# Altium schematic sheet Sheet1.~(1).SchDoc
size 431 x 279 mm; Date: Not shown in title block; ApprovedBy: Not shown in title block; CheckedBy: Not shown in title block; Author: Not shown in title block; CompanyName: Not shown in title block; Engineer: Not shown in title block; Organization: Not shown in title block; Address1: Not shown in title block; Address2: Not shown in title block; Address3: Not shown in title block; Address4: Not shown in title block; DocumentNumber: 1; Revision: Use project parameter SCH_Rev; SheetNumber: 2; SheetTotal: 3; PageSetup: Record=PageOptions¦CenterHorizontal=True¦CenterVertical=True¦PrintScale=1.00¦XCorrection=1.00¦YCorrection=1.00¦PrintKind=0¦BorderSize=5000000¦LeftOffset=0¦BottomOffset=0¦Orientation=2¦PaperLength=1000¦PaperWidth=1000¦Scale=100¦PaperSource=15¦PrintQuality=600¦MediaType=1¦DitherType=10¦PaperKind=Letter¦PrintScaleMode=1
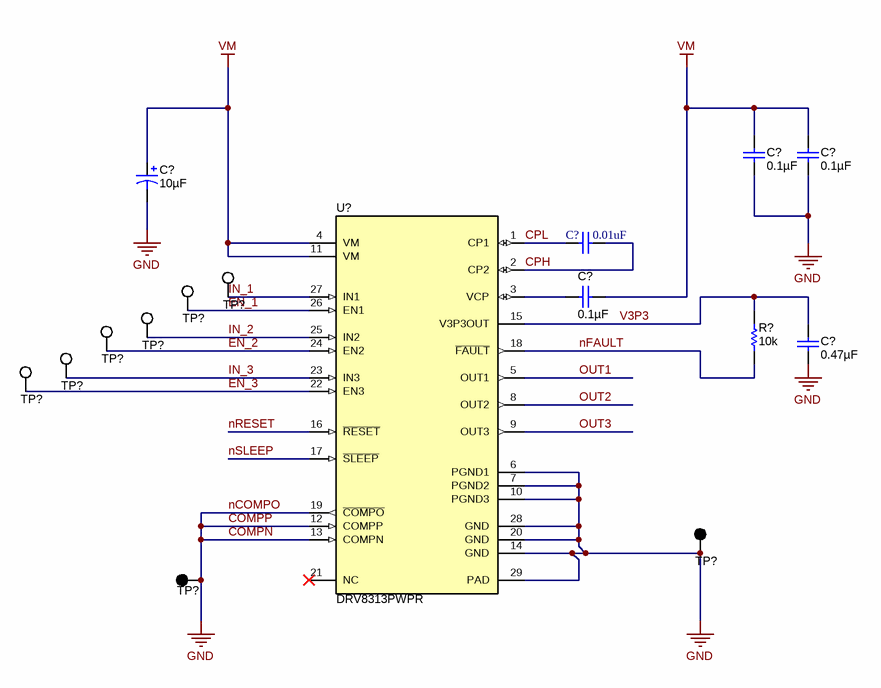
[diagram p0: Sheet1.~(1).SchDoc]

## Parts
(Parts that share a designator on the sheet are numbered #1, #2 ... from top to bottom, then left to right.)
C?#1  ValueDisplayed: 0.1µF  [0805_HV]  (hidden comment: C2012X5R2A104K125AA)
C?#2  ValueDisplayed: 0.1µF  [0805_HV]  (hidden comment: C2012X5R2A104K125AA)
C?#3  ValueDisplayed: 10µF  [SM_RADIAL_D8]  (hidden comment: EEE-FK1K100XP)
C?#4  0.01uF  [0603]
C?#5  ValueDisplayed: 0.1µF  [0805_HV]  (hidden comment: C2012X5R2A104K125AA)
C?#6  ValueDisplayed: 0.47µF  [0603]  (hidden comment: GCM188R71C474KA55D)
R?  ValueDisplayed: 10k  [0805_HV]  (hidden comment: CRCW080510K0JNEA)
TP?#1  5002  [Keystone5002]  (value not drawn)
TP?#2  5002  [Keystone5002]  (value not drawn)
TP?#3  5002  [Keystone5002]  (value not drawn)
TP?#4  5002  [Keystone5002]  (value not drawn)
TP?#5  5002  [Keystone5002]  (value not drawn)
TP?#6  5002  [Keystone5002]  (value not drawn)
TP?#7  5001  [Keystone5001]  (value not drawn)
TP?#8  5001  [Keystone5001]  (value not drawn)
U?  DRV8313PWPR  [PWP0028C_N]

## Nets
COMPN: C?#1.2 C?#2.2 C?#3.2(-) C?#6.2 TP?#7.1 TP?#8.1 U?.6(PGND1) U?.7(PGND2) U?.10(PGND3) U?.12(COMPP) U?.13(COMPN) U?.14(GND) U?.19(~{COMPO}) U?.20(GND) U?.28(GND) U?.29(PAD)  [also labelled COMPP, GND, nCOMPO]
VM: C?#1.1 C?#2.1 C?#3.1(+) C?#5.1 U?.4(VM) U?.11(VM)
CPH: C?#4.1 U?.2(CP2)
CPL: C?#4.2 U?.1(CP1)
EN_1: TP?#2.1 U?.26(EN1)
EN_2: TP?#4.1 U?.24(EN2)
EN_3: TP?#6.1 U?.22(EN3)
IN_1: TP?#1.1 U?.27(IN1)
IN_2: TP?#3.1 U?.25(IN2)
IN_3: TP?#5.1 U?.23(IN3)
nFAULT: R?.2 U?.18(~{FAULT})
nRESET: U?.16(~{RESET})
nSLEEP: U?.17(~{SLEEP})
OUT1: U?.5(OUT1)
OUT2: U?.8(OUT2)
OUT3: U?.9(OUT3)
V3P3: C?#6.1 R?.1 U?.15(V3P3OUT)
NetC?#5_2: C?#5.2 U?.3(VCP)

Not connected (* = marked no-connect by the designer): U? 21(NC)*

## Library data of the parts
C?#1 C?#2 C?#5 = C2012X5R2A104K125AA: CAP, CERM, 0.1 µF, 100 V, +/- 10%, X5R, 0805; Manufacturer: TDK; Polarized: N; CompType: Capacitor; Value: 0.1uF; U/M: EA; Cap_F: 0.0000001; Tolerance_%: 10; ESR_ohm: 0.020726; Value1: 0.020726 ohm; VDC_V: 100; Value2: 100V; IRMS_A: 1.456; TaMin_C: -55; TaMax_C: 85; Cap_Case: 0805; SizeArea_mm2: 2.5; SizeAreaWB_mm2: 6.75; SizeX_mm: 2; SizeY_mm: 1.25; SizeZ_mm: 1.45; AEC Category: Q200
C?#3 = EEE-FK1K100XP: CAP, AL, 10 µF, 80 V, +/- 20%, 2.4 ohm, AEC-Q200 Grade 2, SMD; Manufacturer: Panasonic; Polarized: Y; CompType: Capacitor; Value: 10uF; U/M: EA; Cap_F: 0.00001; Tolerance_%: 20; Value1: 2.4 ohm; VDC_V: 80; Value2: 80V; ESR_ohm: 2.4; IRMS_A: 0.06; TaMin_C: -55; TaMax_C: 105; Cap_Case: D8; SizeAreaWB_mm2: 84.28; SizeArea_mm2: 51.48; SizeX_mm: 7.8; SizeY_mm: 6.6; SizeZ_mm: 7.7; AEC Category: Q200; AEC Grade: 2
C?#4 = Cap: Capacitor; Manufacturer: Murata; MFG Part Number: GCM188R72A103KA37D; Value: .01uF; Cap Voltage: 100V
C?#6 = GCM188R71C474KA55D: CAP, CERM, 0.47 µF, 16 V, +/- 10%, X7R, AEC-Q200 Grade 1, 0603; Manufacturer: MuRata; Polarized: N; CompType: Capacitor; Value: 0.47uF; U/M: EA; Cap_F: 0.00000047; Tolerance_%: 10; Value1: Unknown; VDC_V: 16; Value2: 16V; TaMin_C: -55; TaMax_C: 125; SizeArea_mm2: 1.28; SizeAreaWB_mm2: 4.68; SizeX_mm: 1.6; SizeY_mm: 0.8; SizeZ_mm: 1; AEC Category: Q200; AEC Qualified: Y
R? = CRCW080510K0JNEA: RES, 10 k, 5%, 0.125 W, 0805; Manufacturer: Vishay-Dale; CompType: Resistor; Value: 10k; Res_ohm: 10000; Value_Code: 10k0; Tolerance_%: 5; Power_W: 0.125; Value2: 0.125W; VDC_V: 150; TempCo: 200 ppm/C; SizeArea_mm2: 2.5; SizeX_mm: 2; SizeY_mm: 1.25; SizeZ_mm: 1.45; EIA_Code: E24; U/M: EA; AEC Category: Q200
TP?#1-TP?#6 = 5002: Test Point, Miniature, White, TH; Manufacturer: Keystone; CompType: Test Point Loop; ContactFinish: Silver
TP?#7 TP?#8 = 5001: Test Point, Miniature, Black, TH; Manufacturer: Keystone; CompType: Test Point Loop; ContactFinish: Silver
U? = DRV8313PWPR: Triple Half-H-Bridge Driver IC, PWP0028C; Manufacturer: Texas Instruments; SymbolCreator: x0208325; SizeArea_mm2: 62.08; SizeAreaWB_mm2: 98.28; SizeX_mm: 6.4; SizeY_mm: 9.7; SizeZ_mm: 1.2; U/M: EA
